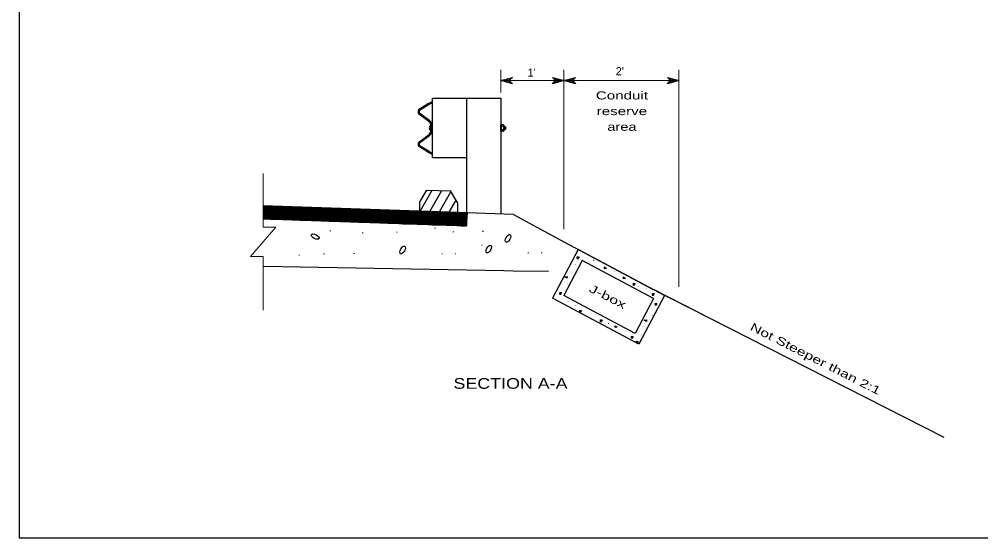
# Model space of a CAD drawing. Extents: x 993470 to 994006, y 1010815 to 1011161.
# Drawn here: x 993470 to 993791.1, y 1010814.9 to 1010988.2 of the extents above; entities that cross this region are included whole.
import ezdxf
from ezdxf.enums import TextEntityAlignment as Align

# ---------------------------------------------------------------- set-up
doc = ezdxf.new("R2010")
doc.units = 0
doc.header["$LTSCALE"] = 0.53
for name, color, linetype, lineweight in [('1', 7, 'Continuous', 25), ('15', 7, 'Continuous', 13), ('16', 7, 'Continuous', 25), ('20', 7, 'Continuous', 13), ('22', 7, 'Continuous', 25), ('3', 7, 'Continuous', 25), ('30', 7, 'Continuous', 25), ('32', 7, 'Continuous', 25)]:
    doc.layers.add(name, color=color, linetype=linetype, lineweight=lineweight)

msp = doc.modelspace()

# ---------------------------------------------------------------- linework, layer by layer
at = {"layer": '1', "lineweight": 13}
for p, q in [((993630.857, 1010971.286), (993630.857, 1010963.638)), ((993651.919, 1010971.286), (993651.919, 1010918.024)), ((993690.319, 1010971.286), (993690.319, 1010898.724))]:
    msp.add_line(p, q, dxfattribs=at)
at = {"layer": '1'}
for p, q in [((993619.455, 1010919.202), (993619.455, 1010961.826)), ((993551.417, 1010925.68), (993555.841, 1010925.68)), ((993551.417, 1010925.508), (993560.907, 1010925.508)), ((993551.417, 1010925.338), (993565.957, 1010925.338)), ((993551.417, 1010925.166), (993571.023, 1010925.166)), ((993551.417, 1010924.994), (993576.075, 1010924.994)), ((993551.417, 1010924.824), (993581.155, 1010924.824)), ((993551.417, 1010924.652), (993586.207, 1010924.652)), ((993551.417, 1010924.482), (993591.287, 1010924.482)), ((993551.417, 1010924.31), (993596.339, 1010924.31)), ((993551.417, 1010924.138), (993601.403, 1010924.138)), ((993551.417, 1010923.968), (993606.455, 1010923.968)), ((993551.417, 1010923.796), (993611.521, 1010923.796)), ((993551.417, 1010923.624), (993616.573, 1010923.624)), ((993551.417, 1010923.454), (993619.741, 1010923.454)), ((993551.417, 1010923.282), (993619.727, 1010923.282)), ((993551.417, 1010923.112), (993619.713, 1010923.112)), ((993551.417, 1010922.94), (993619.713, 1010922.94)), ((993551.417, 1010922.768), (993619.683, 1010922.768)), ((993635.053, 1010922.882), (993619.455, 1010923.426)), ((993635.053, 1010922.882), (993650.621, 1010914.464)), ((993551.417, 1010922.598), (993619.655, 1010922.598)), ((993551.417, 1010922.426), (993619.655, 1010922.426)), ((993551.417, 1010922.254), (993619.641, 1010922.254)), ((993551.417, 1010922.084), (993619.627, 1010922.084)), ((993551.417, 1010921.912), (993619.597, 1010921.912)), ((993551.417, 1010921.742), (993619.597, 1010921.742)), ((993551.417, 1010921.57), (993619.569, 1010921.57)), ((993551.417, 1010921.484), (993619.369, 1010919.102)), ((993553.899, 1010921.398), (993619.555, 1010921.398)), ((993558.809, 1010921.228), (993619.555, 1010921.228)), ((993563.689, 1010921.056), (993619.541, 1010921.056)), ((993568.597, 1010920.886), (993619.513, 1010920.886)), ((993573.493, 1010920.714), (993619.513, 1010920.714)), ((993578.373, 1010920.542), (993619.483, 1010920.542)), ((993583.267, 1010920.372), (993619.469, 1010920.372)), ((993588.175, 1010920.2), (993619.455, 1010920.2)), ((993593.057, 1010920.028), (993619.455, 1010920.028)), ((993597.965, 1010919.858), (993619.427, 1010919.858)), ((993602.845, 1010919.686), (993619.399, 1010919.686)), ((993607.739, 1010919.516), (993619.399, 1010919.516)), ((993612.635, 1010919.344), (993619.383, 1010919.344)), ((993617.515, 1010919.172), (993619.369, 1010919.172)), ((993551.417, 1010905.616), (993631.813, 1010904.204)), ((993635.009, 1010904.132), (993646.797, 1010903.932)), ((993700.765, 1010888.208), (993681.501, 1010898.024)), ((993778.891, 1010848.394), (993700.765, 1010888.208))]:
    msp.add_line(p, q, dxfattribs=at)
for points in [[(993608.039, 1010961.826), (993630.857, 1010961.826), (993630.857, 1010923.04)], [(993619.455, 1010941.862), (993608.039, 1010941.862), (993608.039, 1010961.826)], [(993551.417, 1010921.484), (993619.369, 1010919.102), (993619.741, 1010923.51), (993551.417, 1010925.822)]]:
    msp.add_lwpolyline(points, dxfattribs=at)
for centre, major_axis in [((993568.8441, 1010915.5328), (1.2443, -0.6901)), ((993633.2326, 1010914.9466), (-0.6901, -1.2443)), ((993598.0433, 1010911.0724), (-0.6901, -1.2443)), ((993626.7897, 1010911.3506), (-0.6901, -1.2443))]:
    msp.add_ellipse(centre, major_axis=major_axis, ratio=0.46569, dxfattribs=at)
at = {"layer": '15'}
for p, q in [((993551.417, 1010936.64), (993551.417, 1010918.678)), ((993551.417, 1010908.916), (993551.417, 1010890.954))]:
    msp.add_line(p, q, dxfattribs=at)
msp.add_lwpolyline([(993551.417, 1010918.678), (993555.651, 1010918.678), (993547.184, 1010908.916), (993551.417, 1010908.916)], dxfattribs=at)
at = {"layer": '16'}
for points in [[(993634.111, 1010967.262), (993634.709, 1010966.634), (993630.857, 1010967.69), (993634.709, 1010968.746), (993634.111, 1010968.118), (993630.857, 1010967.69), (993634.111, 1010967.262), (993633.683, 1010967.69), (993634.111, 1010968.118)], [(993648.665, 1010968.118), (993648.067, 1010968.746), (993651.919, 1010967.69), (993648.067, 1010966.634), (993648.665, 1010967.262), (993651.919, 1010967.69), (993648.665, 1010968.118), (993649.093, 1010967.69), (993648.665, 1010967.262)], [(993655.173, 1010967.262), (993655.771, 1010966.634), (993651.919, 1010967.69), (993655.771, 1010968.746), (993655.173, 1010968.118), (993651.919, 1010967.69), (993655.173, 1010967.262), (993654.745, 1010967.69), (993655.173, 1010968.118)], [(993687.065, 1010968.118), (993686.467, 1010968.746), (993690.319, 1010967.69), (993686.467, 1010966.634), (993687.065, 1010967.262), (993690.319, 1010967.69), (993687.065, 1010968.118), (993687.493, 1010967.69), (993687.065, 1010967.262)]]:
    msp.add_lwpolyline(points, dxfattribs=at)
at = {"layer": '22'}
msp.add_line((993700.765, 1010888.208), (993682.013, 1010897.796), dxfattribs=at)
at = {"layer": '3'}
for p, q in [((993656.686, 1010911.185), (993648.053, 1010894.918)), ((993685.552, 1010895.867), (993656.686, 1010911.185)), ((993658.054, 1010907.534), (993651.843, 1010895.831)), ((993681.882, 1010894.889), (993658.054, 1010907.534)), ((993676.897, 1010879.611), (993648.053, 1010894.918)), ((993675.672, 1010883.186), (993651.843, 1010895.831)), ((993681.882, 1010894.889), (993675.672, 1010883.186)), ((993685.552, 1010895.867), (993676.897, 1010879.611))]:
    msp.add_line(p, q, dxfattribs=at)
at = {"layer": '30'}
for p, q in [((993469.979, 1011161.474), (993469.979, 1010814.89)), ((993469.979, 1010814.89), (994005.609, 1010814.89))]:
    msp.add_line(p, q, dxfattribs=at)
at = {"layer": '32', "lineweight": 13}
for p in [(993630.857, 1010967.69), (993690.319, 1010967.69)]:
    msp.add_line(p, (993651.919, 1010967.69), dxfattribs=at)
at = {"layer": '32'}
for p, q in [((993606.669, 1010959.984), (993603.359, 1010957.886)), ((993606.869, 1010959.684), (993603.645, 1010957.63)), ((993606.669, 1010959.984), (993608.067, 1010960.64)), ((993607.839, 1010960.156), (993606.813, 1010959.67)), ((993606.813, 1010954.02), (993603.359, 1010956.602)), ((993607.097, 1010954.22), (993603.673, 1010956.774)), ((993607.483, 1010950.766), (993607.483, 1010952.92)), ((993607.839, 1010950.766), (993607.839, 1010952.92)), ((993631.713, 1010952.878), (993630.871, 1010952.878)), ((993630.871, 1010950.738), (993630.871, 1010952.878)), ((993631.755, 1010952.336), (993630.871, 1010952.336)), ((993631.043, 1010950.766), (993631.043, 1010952.92)), ((993631.885, 1010952.678), (993631.885, 1010950.908)), ((993631.969, 1010952.15), (993632.069, 1010951.45)), ((993632.155, 1010952.164), (993632.269, 1010951.422)), ((993632.397, 1010952.194), (993632.355, 1010952.136)), ((993632.483, 1010951.48), (993632.469, 1010952.15)), ((993603.359, 1010947.014), (993606.527, 1010949.424)), ((993603.631, 1010946.856), (993606.669, 1010949.11)), ((993631.727, 1010950.738), (993630.871, 1010950.738)), ((993631.755, 1010951.252), (993630.899, 1010951.252)), ((993606.669, 1010943.632), (993603.359, 1010945.728)), ((993606.869, 1010943.93), (993603.545, 1010946.028)), ((993607.839, 1010943.074), (993606.669, 1010943.632)), ((993607.839, 1010943.46), (993606.813, 1010943.946)), ((993603.645, 1010926.978), (993606.155, 1010931.074)), ((993603.845, 1010924.024), (993607.897, 1010931.002)), ((993606.155, 1010931.074), (993614.005, 1010930.788)), ((993607.069, 1010923.91), (993611.121, 1010930.902)), ((993610.309, 1010923.796), (993614.175, 1010930.488)), ((993616.515, 1010926.708), (993614.005, 1010930.788)), ((993603.645, 1010926.978), (993603.645, 1010924.11)), ((993613.547, 1010923.682), (993615.873, 1010927.734)), ((993616.515, 1010923.596), (993616.515, 1010926.708)), ((993599.563, 1010924.138), (993615.873, 1010923.568)), ((993615.873, 1010923.568), (993619.455, 1010923.454)), ((993650.621, 1010914.464), (993681.501, 1010898.024)), ((993631.813, 1010904.204), (993635.009, 1010904.132))]:
    msp.add_line(p, q, dxfattribs=at)
for points in [[(993632.469, 1010952.15), (993632.397, 1010952.194), (993632.413, 1010951.822), (993632.355, 1010952.15), (993632.241, 1010952.308), (993632.155, 1010952.164), (993632.055, 1010952.308), (993631.969, 1010952.15), (993631.885, 1010952.25)], [(993631.885, 1010951.45), (993631.985, 1010951.294), (993632.069, 1010951.45), (993632.213, 1010951.308), (993632.269, 1010951.422), (993632.355, 1010951.336), (993632.483, 1010951.48)]]:
    msp.add_lwpolyline(points, dxfattribs=at)
for points in [[(993656.388, 1010908.775), (993656.96, 1010908.747), (993656.446, 1010908.033)], [(993665.447, 1010904.818), (993665.461, 1010905.388), (993666.175, 1010904.888)], [(993652.95, 1010902.155), (993652.906, 1010901.597), (993652.222, 1010902.111)], [(993671.783, 1010901.478), (993671.797, 1010902.048), (993672.511, 1010901.55)], [(993675.095, 1010899.962), (993675.651, 1010899.92), (993675.137, 1010899.234)], [(993650.566, 1010896.847), (993651.108, 1010896.817), (993650.624, 1010896.119)], [(993681.55, 1010896.531), (993682.078, 1010896.503), (993681.58, 1010895.789)], [(993657.224, 1010890.901), (993657.782, 1010890.857), (993657.268, 1010890.173)], [(993682.426, 1010893.211), (993682.996, 1010893.183), (993682.496, 1010892.483)], [(993664.146, 1010887.703), (993664.688, 1010887.675), (993664.174, 1010886.991)], [(993679.486, 1010887.675), (993679.458, 1010887.131), (993678.744, 1010887.617)], [(993668.998, 1010885.193), (993669.026, 1010885.735), (993669.726, 1010885.249)], [(993674.534, 1010882.225), (993675.076, 1010882.209), (993674.592, 1010881.511)], [(993676.588, 1010880.583), (993676.574, 1010880.027), (993675.876, 1010880.511)]]:
    msp.add_lwpolyline(points, close=True, dxfattribs=at)
for centre, radius, start, end in [((993604.6094, 1010957.2349), 1.4088, 153.09947, 206.90052), ((993604.6094, 1010957.2349), 1.0463, 157.53258, 206.90052), ((993605.8677, 1010952.677), 1.6245, 6.77313, 54.60304), ((993608.2518, 1010951.8333), 1.3277, 125.79399, 234.20601), ((993605.8677, 1010952.677), 1.978, 6.77313, 51.41026), ((993631.6675, 1010952.6798), 0.198, 358.66985, 78.95033), ((993630.4198, 1010951.7906), 1.4378, 337.76144, 22.22598), ((993631.3573, 1010952.6491), 0.5088, 320.65926, 1.87123), ((993605.7395, 1010951.0046), 1.7535, 296.1075, 353.23558), ((993605.7395, 1010951.0046), 2.1071, 296.10751, 353.23559), ((993631.5357, 1010951.0229), 0.3518, 303.72238, 339.70691), ((993630.8948, 1010950.7719), 0.9823, 7.37722, 29.19334), ((993604.6094, 1010946.3639), 1.4088, 153.09947, 206.90052), ((993604.6094, 1010946.3639), 1.1081, 153.09947, 196.87803)]:
    msp.add_arc(centre, radius, start, end, dxfattribs=at)

# ---------------------------------------------------------------- texts
at = {"layer": '1'}
for p in [(993574.105, 1010917.4525), (993584.923, 1010916.8105), (993596.309, 1010917.0245), (993609.025, 1010918.3105), (993615.145, 1010917.0965), (993625.049, 1010917.2965), (993571.993, 1010909.7325), (993582.039, 1010909.9325), (993611.465, 1010909.7905), (993615.917, 1010909.8185), (993624.707, 1010912.7025), (993640.203, 1010910.0765), (993644.655, 1010910.0905), (993563.689, 1010909.3045), (993662.013, 1010907.6605), (993667.004, 1010886.4695)]:
    msp.add_text('.', height=2.674, rotation=90, dxfattribs=at).set_placement(p, align=Align.CENTER)
at = {"layer": '20'}
for s, p in [("1'", (993641.1345, 1010968.988)), ("2'", (993670.5725, 1010969.474))]:
    msp.add_text(s, height=2.697, dxfattribs=at).set_placement(p, align=Align.CENTER)
for s, height, width, p in [('Conduit', 2.697, 1.4, (993671.276, 1010961.368)), ('reserve', 2.697, 1.4, (993671.28, 1010956.132)), ('area', 2.697, 1.35, (993671.284, 1010950.894)), ('SECTION A-A', 3.567, 1.25, (993634.066, 1010864.676))]:
    msp.add_text(s, height=height, dxfattribs=dict(at, width=width)).set_placement(p, align=Align.CENTER)
for s, width, p in [('J-box', 1.5, (993665.9043, 1010894.2871)), ('Not Steeper than 2:1', 1.45, (993735.3403, 1010873.5208))]:
    msp.add_text(s, height=2.697, rotation=333, dxfattribs=dict(at, width=width)).set_placement(p, align=Align.CENTER)
at = {"layer": '32'}
for rotation, p in [(63, (993654.7063, 1010903.622)), (63, (993655.9193, 1010906.096)), (153, (993668.884, 1010903.9463)), (63, (993653.0663, 1010899.668)), (153, (993676.753, 1010899.0133)), (63, (993679.6273, 1010898.032)), (63, (993653.3873, 1010893.854)), (153, (993655.757, 1010892.6713)), (63, (993681.4053, 1010891.212)), (153, (993662.665, 1010889.4753)), (63, (993681.6283, 1010889.028)), (63, (993678.3903, 1010885.49)), (153, (993672.486, 1010883.8953)), (63, (993677.9903, 1010882.592))]:
    msp.add_text('.', height=1.337, rotation=rotation, dxfattribs=at).set_placement(p, align=Align.CENTER)

doc.saveas('drawing.dxf')
